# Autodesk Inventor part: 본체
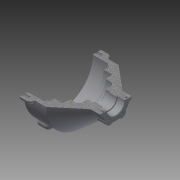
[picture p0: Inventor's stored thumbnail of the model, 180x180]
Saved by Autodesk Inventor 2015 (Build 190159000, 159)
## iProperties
Created: 2026-05
Part Number: 본체
Material: 일반
Document SubType Name: Modeling
Designer: 104
Density: 1 g/cm^3
Appearance: 기본값
Author: 104
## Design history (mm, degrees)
sketch "스케치2"
  geometry: C1 r 82 at (0, 0); 1 further point
  constraints: 1 centre point, 1 coincident
  dimensions: "d0" = 164 diameter of C1
extrude "돌출1" new body sketch "스케치2" distance "d1" = 50; taper "d2" = 0 deg
node "작업 평면1"
sketch "스케치3"
  geometry: C1 r 30.5 at (0, 0); 1 further point
  constraints: 1 centre point, 1 coincident
  dimensions: "d4" = 61 diameter of C1
extrude "돌출2" join sketch "스케치3" stored distance "d5" = 16; taper "d6" = 0 deg
node "작업 평면2"
sketch "스케치4"
  geometry: L1 (0, 82)-(0, -82) reference; L2 (0, -82)-(-50, -82) reference; L3 (-50, -82)-(-50, -30.5) reference; L4 (-50, -30.5)-(-126, -30.5) reference; L5 (-126, -30.5)-(-126, 30.5) reference; L6 (-126, 30.5)-(-50, 30.5) reference; L7 (-50, 30.5)-(-50, 82) reference; L8 (-50, 82)-(0, 82) reference; L9 (-50, 82)-(-111.375, 30.5); L10 (-50, 82)-(30.12, 82); L11 (61.344, 0)-(-157.224, 0) reference; 1 further point
  constraints: 4 end point, 1 equal length, 1 horizontal, 1 point on line
  dimensions: "d8" = 140 deg angle of L9 L10
revolve "회전1" sketch "스케치4" stored, may be unused: angle "d9" = 90 deg
sketch "스케치5"
  geometry: C1 r 82 at (0, 0) reference; C2 r 73 at (0, 0)
  constraints: 1 centre point, 1 coincident
  dimensions: "d10" = 146 diameter of C2
extrude "돌출3" cut sketch "스케치5" distance "d11" = 37; taper "d12" = 0 deg
sketch "스케치6"
  geometry: C1 r 73 at (0, 0) reference; C2 r 68 at (0, 0)
  constraints: 1 centre point, 1 coincident
  dimensions: "d13" = 136 diameter of C2
extrude "돌출4" cut sketch "스케치6" distance "d14" = 5; taper "d15" = 0 deg
sketch "스케치10"
  geometry: C1 r 30.5 at (0, 0) reference
hole "구멍1" sketch "스케치10" at (0, 0) diameter "d25" = 35; stored, may be unused: countersink angle "d29" = 82 deg, drill point angle "d31" = 0 deg; dims "d26" = 5.984, "d27" = 40, "d28" = 16, "d30" = 10.688
sketch "스케치12"
  geometry: C1 r 17.5 at (0, 0) reference; C2 r 68 at (0, 0) reference; C3 r 56 at (0, 0)
  constraints: 1 centre point, 1 coincident
  dimensions: "d32" = 112 diameter of C3
extrude "돌출8" cut sketch "스케치12" distance "d33" = 20; taper "d34" = 0 deg
sketch "스케치13"
  geometry: C1 r 17.5 at (0, 0) reference; C2 r 56 at (0, 0) reference; C3 r 40 at (0, 0)
  constraints: 1 centre point, 1 coincident
  dimensions: "d35" = 80 diameter of C3
extrude "돌출9" cut sketch "스케치13" distance "d36" = 16; taper "d37" = 0 deg
sketch "스케치14"
  geometry: C1 r 17.5 at (0, 0) reference; C2 r 40 at (0, 0) reference; C3 r 37 at (0, 0)
  constraints: 1 centre point, 1 coincident
  dimensions: "d38" = 74 diameter of C3
extrude "돌출10" cut sketch "스케치14" distance "d39" = 4; taper "d40" = 0 deg
sketch "스케치15"
  geometry: C1 r 17.5 at (0, 0) reference; C2 r 30.5 at (0, 0) reference; C3 r 20 at (0, 0)
  constraints: 1 centre point, 1 coincident
  dimensions: "d41" = 40 diameter of C3
extrude "돌출11" cut sketch "스케치15" distance "d42" = 12; taper "d43" = 0 deg
sketch "스케치16"
  geometry: L1 (0, 27)-(23.383, 13.5); L2 (23.383, 13.5)-(23.383, -13.5); L3 (23.383, -13.5)-(0, -27); L4 (0, -27)-(-23.383, -13.5); L5 (-23.383, -13.5)-(-23.383, 13.5); L6 (-23.383, 13.5)-(0, 27); A1 r 20 centre (0, 0) between (-14.391, -13.889) and (-19.224, -5.519) reference; A2 r 9 centre (-23.383, -13.5) between (-19.224, -5.519) and (-14.391, -13.889); 1 further point
  constraints: 12 end point, 4 point on circle, 1 centre point, 1 coincident, 13 other
  dimensions: "d45" = 18 diameter of A2
extrude "돌출12" join sketch "스케치16" stored distance "d46" = 0; taper "d47" = 0 deg
sketch "스케치17"
  geometry: A1 r 9 centre (0, -27) between (-8.72, -29.227) and (8.72, -29.227) reference; A2 r 9 centre (23.383, -13.5) between (20.951, -22.165) and (29.671, -7.062) reference; A3 r 9 centre (23.383, 13.5) between (29.671, 7.062) and (20.951, 22.165) reference; A4 r 9 centre (0, 27) between (8.72, 29.227) and (-8.72, 29.227) reference; A5 r 9 centre (-23.383, 13.5) between (-20.951, 22.165) and (-29.671, 7.062) reference; A6 r 9 centre (-23.383, -13.5) between (-29.671, -7.062) and (-20.951, -22.165) reference
hole "구멍2" sketch "스케치17" at (-23.383, 13.5), (0, 27), (23.383, 13.5), (23.383, -13.5), (0, -27), (-23.383, -13.5) diameter "d51" = 3.242; stored, may be unused: countersink angle "d55" = 82 deg, drill point angle "d57" = 118 deg; dims "d52" = 8, "d53" = 40, "d54" = 16, "d56" = 10
node "작업 평면3"
sketch "스케치18"
  geometry: L1 (0, -82)-(-71.014, -41); L2 (-71.014, -41)-(-71.014, 41); L3 (-71.014, 41)-(0, 82); L4 (0, 82)-(71.014, 41); L5 (71.014, 41)-(71.014, -41); L6 (71.014, -41)-(0, -82); A1 r 10 centre (71.014, 41) between (71.014, 31) and (62.354, 46); 3 further points
  constraints: 12 end point, 2 point on circle, 2 point on line, 1 centre point, 1 coincident, 1 vertical alignment, 14 other
  dimensions: "d60" = 20 diameter of A1
extrude "돌출13" join sketch "스케치18" distance "d61" = 15; taper "d62" = 0 deg
sketch "스케치19"
  geometry: C1 r 10 at (-71.014, 41); A1 r 82 centre (0, 0) between (-65.495, 49.339) and (-75.477, 32.051) reference; A2 r 10 centre (-71.014, 41) between (-65.495, 49.339) and (-75.477, 32.051) reference
  constraints: 1 centre point, 1 coincident, 1 concentric
extrude "돌출14" join sketch "스케치19" distance "d63" = 10; taper "d64" = 0 deg
fillet "모깎기1" dims "d65" = 10
sketch "스케치20"
  geometry: A1 r 10 centre (71.014, 41) between (75.477, 32.051) and (65.495, 49.339) reference; A2 r 10 centre (0, 82) between (9.981, 81.39) and (-9.981, 81.39) reference; A3 r 10 centre (-71.014, 41) between (-65.495, 49.339) and (-75.477, 32.051) reference; A4 r 10 centre (-71.014, -41) between (-75.477, -32.051) and (-65.495, -49.339) reference; A5 r 10 centre (0, -82) between (-9.981, -81.39) and (9.981, -81.39) reference; A6 r 10 centre (71.014, -41) between (65.495, -49.339) and (75.477, -32.051) reference
hole "구멍3" sketch "스케치20" at (0, -82), (-71.014, -41), (-71.014, 41), (0, 82), (71.014, 41), (71.014, -41) diameter "d69" = 4.917; stored, may be unused: countersink angle "d73" = 82 deg, drill point angle "d75" = 118 deg; dims "d70" = 12, "d71" = 40, "d72" = 16, "d74" = 14
sketch "스케치21"
  geometry: L1 (0, 62)-(53.694, 31); L2 (53.694, 31)-(53.694, -31); L3 (53.694, -31)-(0, -62); L4 (0, -62)-(-53.694, -31); L5 (-53.694, -31)-(-53.694, 31); L6 (-53.694, 31)-(0, 62); 1 further point
  constraints: 12 end point, 13 other
hole "구멍4" sketch "스케치21" at (0, 62), (53.694, 31), (53.694, -31), (0, -62), (-53.694, -31), (-53.694, 31) diameter "d77" = 3.242; stored, may be unused: countersink angle "d81" = 82 deg, drill point angle "d83" = 118 deg; dims "d78" = 8, "d79" = 40, "d80" = 16, "d82" = 10
fillet "모깎기2" dims "d84" = 0.6
fillet "모깎기3" dims "d85" = 1
chamfer "모따기1" distance "d86" = 1; stored, may be unused: second distance "d87" = 2, angle "d88" = 45 deg
fillet "모깎기4" dims "d89" = 3
chamfer "모따기2" distance "d90" = 1; stored, may be unused: second distance "d91" = 2, angle "d92" = 45 deg
fillet "모깎기5" dims "d93" = 3
chamfer "모따기4" distance "d97" = 1; stored, may be unused: second distance "d98" = 2, angle "d99" = 45 deg
fillet "모깎기6" dims "d100" = 3
chamfer "모따기5" distance "d101" = 1; stored, may be unused: second distance "d102" = 2, angle "d103" = 45 deg
fillet "모깎기7" dims "d104" = 3
fillet "모깎기8" dims "d105" = 3
fillet "모깎기9" dims "d106" = 3
node "작업 평면4"
sketch "스케치22"
  geometry: L1 (0, 29.801)-(0, -29.801) reference; 3 further points
  constraints: 1 horizontal alignment, 1 midpoint, 1 other
  dimensions: "d107" = 20 distance from line of L1 point (20, 0)
feature "엠보싱1" sketch "스케치22" dims "d108" = 0.5, "d109" = 0
chamfer "모따기6" distance "d110" = 1; stored, may be unused: second distance "d111" = 2, angle "d112" = 45 deg
node "솔리드1"
pattern_circular "원형 패턴1" dims angle "d49" = 360 deg
pattern_circular "원형 패턴2" dims "d67" = 360 deg
node "절단 모서리 투영1"
other parameters: "d3" = -126, "d7" = 0, "d58" = 0
